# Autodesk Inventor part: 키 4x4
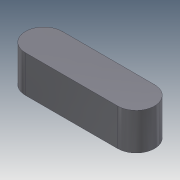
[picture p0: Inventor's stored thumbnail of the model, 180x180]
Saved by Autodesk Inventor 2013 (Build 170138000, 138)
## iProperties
Company: 한국ATC센터
Created: 2014-10
Part Number: 키 4x4
Document SubType Name: Modeling
Designer: KYOUNG IL JANG
Density: 7.85 g/cm^3
Mass: 1.65058 g
Surface Area: 2.35398 cm^2
Volume: 0.210265 cm^3
Material: 강철
Author: KYOUNG IL JANG
Revision Number: 1
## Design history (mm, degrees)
sketch "스케치1"
  geometry: L1 (-5, -2)-(5, -2); L2 (5, 2)-(-5, 2); A1 r 2 centre (5, 0) between (5, -2) and (5, 2); A2 r 2 centre (-5, 0) between (-5, 2) and (-5, -2); 2 further points
  constraints: 4 end point, 4 point on circle, 4 tangent, 2 centre point, 1 horizontal, 1 horizontal alignment, 1 midpoint, 1 parallel, 1 vertical alignment
  dimensions: "d0" = 4 distance between parallel lines of L1 L2; "d1" = 14 dimension on A1 A2
extrude "돌출1" new body sketch "스케치1" stored distance "d2" = 4; taper "d3" = 0 deg
node "솔리드1"
